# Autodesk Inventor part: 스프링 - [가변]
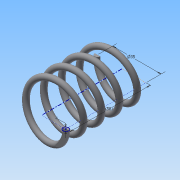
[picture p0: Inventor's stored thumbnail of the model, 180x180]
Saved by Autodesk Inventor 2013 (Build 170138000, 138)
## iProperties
Created: 2015-03
Part Number: 스프링 - [가변]
Material: 일반
Document SubType Name: Modeling
Designer: Administrator
Density: 1 g/cm^3
Mass: 6.09073 g
Surface Area: 62.0026 cm^2
Volume: 6.09073 cm^3
Author: Administrator
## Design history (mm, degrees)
sketch "스케치1"
  geometry: L1 (0, 0)-(17.5, 0); L2 (17.5, 0)-(17.5, 43.5); L3 (17.5, 43.5)-(0, 43.5); L4 (0, 43.5)-(0, 0); C1 r 2 at (17.5, 0)
  constraints: 8 end point, 2 parallel, 1 centre point, 1 coincident, 1 horizontal, 1 perpendicular
  dimensions: "d0" = 43.5 distance of L1.end L2.end (derived); "d2" = 35 diameter of L2 L4; "d3" = 4 diameter of C1
feature "코일1" sketch "스케치1" pitch "d4" = 10; turns "d6" = 4.5; dims "d5" = 43.5 (= d0), "d7" = 0, angle "d8" = 90 deg, angle "d9" = 90 deg, "d10" = 0, "d11" = 0
node "작업 평면1"
sketch "스케치2"
  geometry: L1 (15.5, 0)-(19.5, 0) reference; 1 further point
  constraints: 1 horizontal alignment
extrude "돌출1" cut sketch "스케치2" stored distance "d13" = 10; taper "d14" = 0 deg
node "작업 평면2"
sketch "스케치3"
  geometry: L1 (15.5, 0)-(19.5, 0) reference; 1 further point
  constraints: 1 horizontal alignment
extrude "돌출2" cut sketch "스케치3" stored distance "d16" = 10; taper "d17" = 0 deg
node "솔리드1"
node "절단 모서리 투영1"
node "절단 모서리 투영2"
other parameters: "d12" = 0, "d15" = -43.5 (= -d0)
